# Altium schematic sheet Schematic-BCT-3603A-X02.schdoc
size 297 x 209 mm; Symbol: Drawing-Symbol_A4; Version: V1.0; Page Size: A4; @Project Name: BCT-360X-001; @Page Count: 1; @Update Date: 2025-11-11; @Create Date: 2025-09-30; @Schematic Name: Schematic1_1; @Page No: 1; @Page Name: P1; @Create Time: 05:19:14; @Update Time: 09:37:58; Border: 1; Width: 1170; Height: 825; Region Start: 1; X Region Count: 6; Y Region Count: 4; Blade Width: 10; Title Block Position: 3; @Board Name: BCT-3603-14; Device: Drawing-Symbol_A4
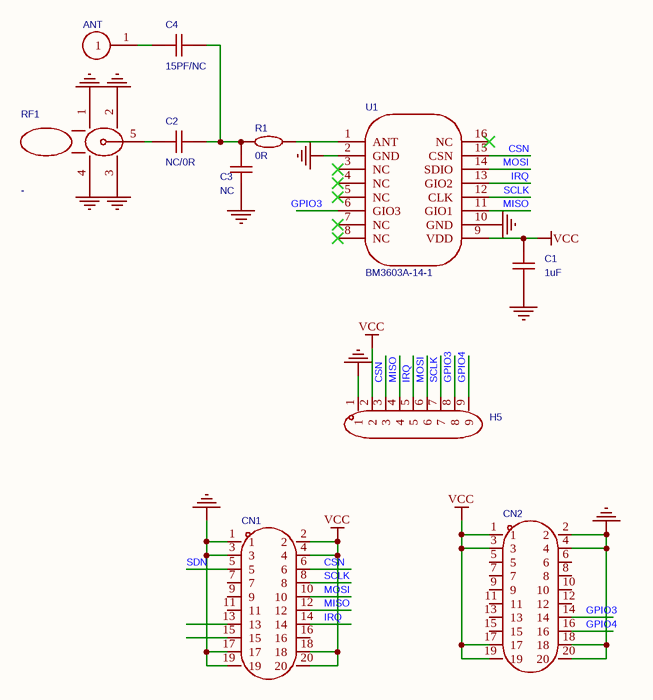
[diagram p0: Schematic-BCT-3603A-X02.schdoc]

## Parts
ANT  PZ254V-11-01P  [HDR-TH_1P-P2.54-V-M]  (value not drawn)
C1  1uF  [0402C]
C2  NC/0R  [0402C]
C3  NC  [0402C]
C4  15PF/NC  [0402C]
CN1  2345-210MG3DUNP3  [BB02-CL]  (value not drawn)
CN2  2345-210MG3DUNP3  [BB02-CL]  (value not drawn)
H5  PZ254V-11-09P  [HDR-TH_9P-P2.54-V-M]  (value not drawn)
R1  0R  [0402L]
RF1  -  [SMA-TH_BWSMA-KE-Z001]
U1  BM3603A-14-1  [BM3603-14-1]

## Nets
GND: C1.2 C3.2 CN1.1 CN1.3 CN1.17 CN1.19 CN2.2 CN2.4 CN2.18 CN2.20 H5.1 RF1.1 RF1.2 RF1.3 RF1.4 U1.2(GND) U1.10(GND)
VCC: C1.1 CN1.2 CN1.4 CN1.18 CN1.20 CN2.1 CN2.3 CN2.17 CN2.19 H5.2 U1.9(VDD)
CSN: CN1.6 H5.3 U1.15(CSN)
GPIO3: CN2.14 H5.8 U1.6(GIO3)
GPIO4: CN2.16 H5.9
IRQ: CN1.14 H5.5 U1.13(GIO2)
MISO: CN1.12 H5.4 U1.11(GIO1)
MOSI: CN1.10 H5.6 U1.14(SDIO)
SCLK: CN1.8 H5.7 U1.12(CLK)
SDN: CN1.5
NetANT_1: ANT.1 C4.2
NetC2_1: C2.1 C3.1 C4.1 R1.2
NetC2_2: C2.2 RF1.5
NetR1_1: R1.1 U1.1(ANT)

Not connected (* = marked no-connect by the designer): CN1 7 9 11 13 15 16; CN2 5 6 7 8 9 10 11 12 13 15; U1 3(NC)* 4(NC)* 5(NC)* 7(NC)* 8(NC)* 16(NC)*

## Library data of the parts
ANT = PZ254V-11-01P: AddInBom: yes; ModelId: efa57846279b44bfa0a28253a2c74e33; ModelName: HDR2.54-M-LI-1X1P; ModelTransform: 100,100,0,0,0,0,0,0,-118.11; Pin Structure: 1x1P; Pitch: 2.54mm
C1 = CL10A105KB8NNNC: AddInBom: yes; ModelId: ac125912035d415993ca9572d50418b1; ModelName: C0603_L1.6-W0.8-H0.8; ModelTransform: 62.992,31.496,0,0,0,0,0,0,0; Voltage Rating: 50V; Temperature Coefficient: X5R
C2-C4 = CL05A105KA5NQNC: AddInBom: yes; ModelId: 36a51122f27c49738f86b3bfa98863e0; ModelName: C0402_L1.0-W0.5-H0.5; ModelTransform: 39.37,19.685,0,0,0,0,0,0,0; Voltage Rating: 25V; Temperature Coefficient: X5R
CN1 CN2 = 2345-210MG3DUNP3: AddInBom: yes; ModelId: 2585ed06fa9d440a83fe7daa0661b53f; ModelName: CONN-SMD_2345-210MG3DUNP3; ModelTransform: 514.9596,164.9603,0,0,0,0,0,-0.002,0; Number of Holes: 20P; Pitch: 1.27mm; Holes Structure: 2x10P; Current Rating (Max): 1A
H5 = PZ254V-11-09P: AddInBom: yes; ModelId: b5c1e988b3bb4503807579736b357ad0; ModelName: HDR-TH_9P-P2.54-M-LI-1X9P; ModelTransform: 890.15562,98.425,0,0,0,0,0,0,-118.11; Pin Structure: 1x9P; Pitch: 2.54mm
R1 = 0402WGF0000TCE: AddInBom: yes; ModelId: 98c88bc2b9094f218f3a3e30a7012738; ModelName: R0402_L1.0-W0.5-H0.4; ModelTransform: 39.37,19.685,0,0,0,0,0,0,0; Power(Watts): 62.5mW; Voltage-Supply(Max): 50V
RF1 = BWSMA-KE-Z001_C496549: AddInBom: yes; ModelId: 001406414292416eaa06b3346c29c082; ModelName: SMA-TH_5P-L6.5-W6.5-H9.8_BWSMA-KE-Z001; ModelTransform: 255.905,255.905,0,0,0,0,0,0,-137.795; Number of Ports: 1; RF Series: SMA
U1 = BM3606-14-1: AddInBom: yes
